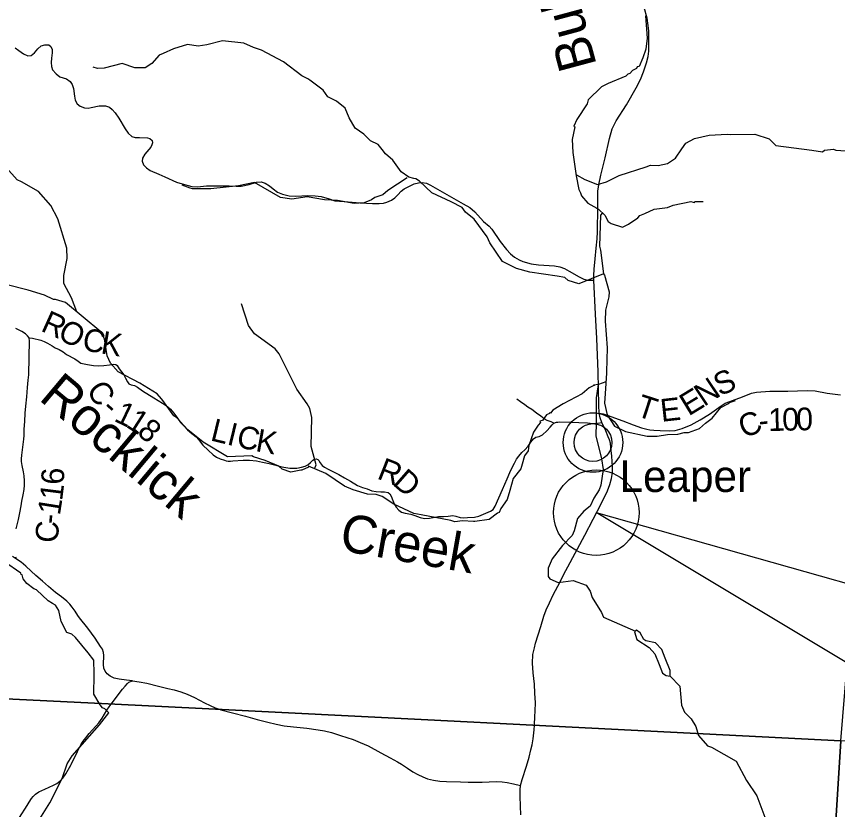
# Model space of a CAD drawing. Extents: x -1.8 to 75.7, y -2 to 25.
# Drawn here: x 45.89 to 47.944, y 18.595 to 20.577 of the extents above; entities that cross this region are included whole.
import ezdxf

# ---------------------------------------------------------------- set-up
doc = ezdxf.new("R2010")
doc.units = 0
for name, color, linetype in [('GM_X_County_Road', 7, 'Continuous'), ('GM_X_County_Road_Text', 7, 'Continuous'), ('GM_X_Minor_River', 7, 'Continuous'), ('GM_X_Minor_River_Text', 7, 'Continuous'), ('GM_X_State_Route', 7, 'Continuous'), ('GM_X_Township', 7, 'Continuous'), ('GM_X_Township_Road', 7, 'Continuous'), ('GM_X_Unincorporated', 7, 'Continuous'), ('GM_X_Unincorporated_Location', 7, 'Continuous'), ('GM_X_Unincorporated_Text', 7, 'Continuous'), ('TX_P_1', 7, 'Continuous')]:
    doc.layers.add(name, color=color, linetype=linetype)

msp = doc.modelspace()

# ---------------------------------------------------------------- linework, layer by layer
at = {"layer": 'GM_X_County_Road'}
for points in [[(45.8872, 20.4988), (45.896, 20.4924), (45.9077, 20.4835), (45.9186, 20.4785), (45.9274, 20.48), (45.9355, 20.4864), (45.9442, 20.4963), (45.9524, 20.5034), (45.9615, 20.5067), (45.9714, 20.5059), (45.9767, 20.5018), (45.9795, 20.495), (45.9799, 20.4864), (45.9784, 20.4734), (45.9773, 20.4621), (45.9784, 20.4521), (45.9805, 20.444), (45.9895, 20.4335), (45.9991, 20.4262), (46.0153, 20.4211), (46.0247, 20.4143), (46.0301, 20.4073), (46.033, 20.3968), (46.0352, 20.3782), (46.0373, 20.368), (46.0424, 20.3588), (46.0497, 20.3528), (46.0604, 20.3492), (46.0696, 20.3481), (46.0772, 20.3494), (46.0977, 20.3539), (46.1129, 20.3541), (46.1229, 20.3509), (46.1302, 20.3451), (46.1376, 20.3366), (46.1462, 20.3227), (46.1622, 20.296), (46.1699, 20.2854), (46.1791, 20.2775), (46.1874, 20.2751), (46.1978, 20.2743), (46.2185, 20.274), (46.2243, 20.2719), (46.2296, 20.2672), (46.2307, 20.261), (46.2294, 20.2561), (46.2262, 20.2506), (46.2113, 20.2331), (46.2055, 20.2228), (46.2051, 20.2158), (46.2081, 20.2066), (46.2158, 20.1985), (46.2247, 20.1923), (46.2463, 20.1831), (46.2614, 20.1761), (46.2909, 20.1633), (46.3103, 20.1571), (46.3287, 20.1524), (46.3432, 20.1511), (46.3656, 20.1537), (46.3949, 20.1543), (46.4224, 20.1543), (46.4399, 20.1532), (46.4525, 20.153), (46.4723, 20.1575), (46.4911, 20.1633), (46.5024, 20.1639), (46.5127, 20.1607), (46.5229, 20.1541), (46.5323, 20.1464), (46.543, 20.1383), (46.5556, 20.1332), (46.5725, 20.1291), (46.5893, 20.1283), (46.6192, 20.1295), (46.6378, 20.1289), (46.6521, 20.1274), (46.6726, 20.1216), (46.6865, 20.1161), (46.7101, 20.115), (46.7503, 20.1118), (46.7808, 20.1101), (46.7975, 20.1101), (46.8083, 20.1108), (46.8167, 20.1129), (46.8286, 20.1184), (46.8363, 20.1238), (46.8442, 20.1315), (46.8524, 20.1402), (46.8596, 20.146), (46.8749, 20.1539), (46.8854, 20.1586), (46.8959, 20.1618), (46.9048, 20.162), (46.9161, 20.1603), (46.9257, 20.1558), (47.0077, 20.1093), (47.0239, 20.0997), (47.0367, 20.0892), (47.0581, 20.0646), (47.0728, 20.0531), (47.079, 20.0459), (47.1001, 20.0151), (47.1157, 19.9944), (47.1258, 19.9837), (47.136, 19.9756), (47.1477, 19.9688), (47.1571, 19.965), (47.1772, 19.959), (47.1962, 19.9566), (47.2361, 19.9543), (47.2494, 19.9511), (47.2609, 19.947), (47.2728, 19.9408), (47.2976, 19.9261), (47.3091, 19.9208), (47.3185, 19.918), (47.3347, 19.9185)], [(45.8896, 19.2966), (45.8953, 19.3199), (45.8993, 19.3366), (45.9019, 19.3538), (45.9037, 19.3661), (45.9069, 19.3817), (45.9094, 19.3947), (45.9107, 19.4055), (45.9109, 19.4163), (45.9094, 19.4289), (45.908, 19.4387), (45.9045, 19.4553), (45.9032, 19.4645), (45.903, 19.4717), (45.9036, 19.4808), (45.9052, 19.4938), (45.9072, 19.5076), (45.9091, 19.521), (45.9096, 19.5299), (45.9098, 19.5457), (45.9111, 19.5648), (45.912, 19.5859), (45.9136, 19.6036), (45.916, 19.6262), (45.9182, 19.65), (45.9201, 19.6678), (45.921, 19.6815), (45.9215, 19.6949), (45.9219, 19.7123), (45.9222, 19.7368), (45.9231, 19.7556), (45.9231, 19.7657), (45.922, 19.7736), (45.9182, 19.7793), (45.9132, 19.7843), (45.9035, 19.7901), (45.889, 19.7969)], [(45.922, 19.7736), (45.9308, 19.773), (45.9516, 19.7678), (45.9595, 19.7651), (45.9679, 19.761), (45.9796, 19.754), (45.9873, 19.7494), (45.997, 19.7449), (46.0074, 19.7386), (46.016, 19.7323), (46.0361, 19.7217), (46.0449, 19.7154), (46.0512, 19.7106), (46.0682, 19.707), (46.0835, 19.7047), (46.0944, 19.7036), (46.1091, 19.705), (46.1228, 19.7061), (46.1339, 19.7081), (46.1386, 19.7072), (46.142, 19.7052), (46.1475, 19.6966), (46.1588, 19.6815), (46.1635, 19.6733), (46.1678, 19.6638), (46.1716, 19.6593), (46.1775, 19.6566), (46.1854, 19.6548), (46.1931, 19.6507), (46.2057, 19.6419), (46.2344, 19.6236), (46.2554, 19.6105), (46.2681, 19.602), (46.2758, 19.5959), (46.2841, 19.5859), (46.2929, 19.573), (46.3006, 19.5626), (46.309, 19.5538), (46.318, 19.5441), (46.3289, 19.5351), (46.3395, 19.5267), (46.3456, 19.5195), (46.3562, 19.5059), (46.3695, 19.4935), (46.3824, 19.4818), (46.3908, 19.4754), (46.4002, 19.4712), (46.4104, 19.4684), (46.4149, 19.4669), (46.4203, 19.4657), (46.426, 19.4657), (46.4314, 19.4664), (46.4572, 19.4682), (46.4734, 19.468), (46.4908, 19.4662), (46.5057, 19.4635), (46.5222, 19.4603), (46.536, 19.4569), (46.5475, 19.4529), (46.5595, 19.4504), (46.5742, 19.4483), (46.583, 19.4479), (46.592, 19.4483), (46.6035, 19.4511), (46.6121, 19.4533), (46.6187, 19.4567), (46.6255, 19.4626), (46.6316, 19.4678), (46.6354, 19.4703), (46.6397, 19.4712), (46.6438, 19.47), (46.6469, 19.4671), (46.6503, 19.4612), (46.6548, 19.4551), (46.6609, 19.4506), (46.67, 19.4459), (46.6837, 19.4393), (46.6968, 19.4328), (46.7108, 19.4244), (46.7258, 19.4156), (46.7432, 19.4052), (46.756, 19.3998), (46.7671, 19.3964), (46.7788, 19.3916), (46.7904, 19.3901), (46.8019, 19.3892), (46.8111, 19.3889), (46.8197, 19.3876), (46.8245, 19.3842), (46.8276, 19.3783), (46.8313, 19.3677), (46.8349, 19.3587), (46.8396, 19.3505), (46.8464, 19.3431), (46.8536, 19.3383), (46.8624, 19.3356), (46.8764, 19.3334), (46.8866, 19.3297), (46.9002, 19.325), (46.9105, 19.3225), (46.923, 19.3232), (46.946, 19.3275), (46.9584, 19.3275), (46.9702, 19.3286), (46.9815, 19.3295), (46.9896, 19.3284), (47, 19.3252), (47.0086, 19.3241), (47.0183, 19.3245), (47.0359, 19.3255), (47.0471, 19.3282), (47.0759, 19.3404), (47.0827, 19.3453), (47.0876, 19.353), (47.0878, 19.3534)], [(47.348, 19.5859), (47.3576, 19.5843), (47.3678, 19.581), (47.4068, 19.5663), (47.433, 19.5568), (47.4537, 19.549), (47.4665, 19.5453), (47.4746, 19.5438), (47.4843, 19.5428), (47.5001, 19.5421), (47.523, 19.5414), (47.5375, 19.5425), (47.5552, 19.547), (47.5774, 19.5567), (47.6006, 19.5688), (47.6235, 19.583), (47.6526, 19.604), (47.6628, 19.6106), (47.681, 19.6172), (47.7061, 19.6269), (47.7283, 19.6357), (47.7415, 19.6385), (47.7744, 19.6404), (47.7992, 19.6404), (47.8193, 19.6406), (47.8678, 19.6421), (47.8877, 19.6414), (47.9182, 19.6359), (47.9508, 19.6317)], [(47.0878, 19.3534), (47.1062, 19.3953), (47.1175, 19.4219), (47.1242, 19.4375), (47.131, 19.4517), (47.136, 19.461), (47.141, 19.4703), (47.1466, 19.4786), (47.1542, 19.487), (47.1615, 19.4937), (47.1699, 19.5035), (47.1766, 19.5134), (47.1832, 19.5215), (47.1895, 19.5254), (47.1972, 19.5274), (47.2056, 19.5319), (47.2164, 19.5419), (47.2248, 19.5507), (47.2304, 19.5563), (47.2346, 19.5606), (47.2413, 19.5632), (47.2441, 19.5636)], [(47.2441, 19.5636), (47.2493, 19.5641), (47.2755, 19.5628), (47.3181, 19.5612), (47.3327, 19.5601), (47.3434, 19.5608), (47.354, 19.5626)], [(46.1809, 18.9164), (46.1658, 18.9182), (46.1475, 18.9206), (46.1344, 18.9236), (46.1244, 18.9283), (46.1176, 18.9342), (46.1127, 18.9405), (46.1093, 18.9484), (46.1082, 18.9577), (46.1091, 18.9796), (46.1084, 18.9877), (46.1054, 18.9956), (46.1007, 19.0026), (46.0869, 19.0237), (46.0693, 19.0481), (46.0485, 19.0745), (46.044, 19.0801), (46.037, 19.091), (46.03, 19.1011), (46.0237, 19.1084), (46.0164, 19.1156), (46.0031, 19.1264), (45.9884, 19.1377), (45.9706, 19.1526), (45.9552, 19.1655), (45.939, 19.18), (45.927, 19.1906), (45.9137, 19.203), (45.9021, 19.213), (45.8908, 19.2209), (45.8807, 19.2274)], [(45.8908, 19.2209), (45.8885, 19.2259)]]:
    msp.add_lwpolyline(points, dxfattribs=at)
at = {"layer": 'GM_X_Minor_River'}
for points in [[(47.4634, 20.5784), (47.4676, 20.5233), (47.4646, 20.4952), (47.4571, 20.4742), (47.4473, 20.4522), (47.4424, 20.451), (47.4408, 20.4468), (47.4314, 20.4423), (47.4242, 20.4343), (47.4197, 20.4327), (47.4144, 20.4278), (47.3698, 20.4094), (47.3532, 20.4014), (47.3203, 20.369), (47.3173, 20.3587), (47.292, 20.3199), (47.2845, 20.3031), (47.2868, 20.3013), (47.28, 20.2701), (47.2815, 20.2374), (47.2903, 20.1785), (47.2968, 20.145), (47.3009, 20.1367), (47.3036, 20.1287), (47.3195, 20.1105), (47.3422, 20.098), (47.346, 20.0957), (47.3619, 20.0809), (47.3698, 20.0646), (47.3774, 20.0601), (47.4057, 20.051), (47.4208, 20.0583), (47.4446, 20.0735), (47.4496, 20.08), (47.4616, 20.085), (47.4855, 20.0957), (47.5183, 20.0995), (47.5323, 20.1053), (47.5773, 20.1145), (47.583, 20.1134), (47.5864, 20.1123), (47.5871, 20.1145), (47.6079, 20.1146)], [(47.3582, 19.9338), (47.297, 19.9092), (47.2704, 19.9176), (47.2616, 19.9247), (47.2428, 19.9284), (47.1739, 19.9378), (47.1409, 19.9476), (47.1056, 19.965), (47.0744, 20.0112), (47.0673, 20.0266), (47.035, 20.0702), (47.0136, 20.0884), (47.0049, 20.0997), (46.9777, 20.1138), (46.9293, 20.1366), (46.8984, 20.1657), (46.8888, 20.1713), (46.8843, 20.1722), (46.8719, 20.1753), (46.8526, 20.1892), (46.832, 20.2184), (46.8132, 20.2341), (46.8052, 20.2447), (46.7946, 20.2568), (46.776, 20.2665), (46.7595, 20.283), (46.7376, 20.2981), (46.7225, 20.324), (46.7127, 20.3479), (46.6905, 20.3653), (46.6689, 20.3762), (46.6573, 20.3933), (46.6241, 20.4183), (46.6189, 20.4215), (46.604, 20.4292), (46.5582, 20.4637), (46.5035, 20.4932), (46.4829, 20.4999), (46.459, 20.5102), (46.4055, 20.5164), (46.3663, 20.5063), (46.3447, 20.5032), (46.3179, 20.5071), (46.2828, 20.496), (46.2572, 20.4843), (46.2472, 20.4808), (46.2288, 20.4594), (46.2126, 20.4485), (46.1865, 20.4486), (46.1547, 20.4598), (46.1094, 20.4476), (46.0935, 20.4474), (46.0823, 20.4508)], [(46.0414, 19.839), (46.0278, 19.8743), (46.0086, 19.9099), (46.0089, 19.9301), (46.0173, 19.9723), (46.0164, 19.9977), (45.9943, 20.0717), (45.9767, 20.105), (45.9457, 20.1394), (45.903, 20.1635), (45.8924, 20.1687), (45.8649, 20.1993), (45.8452, 20.2566), (45.8334, 20.3112), (45.834, 20.3507)], [(47.2909, 20.1815), (47.3121, 20.17), (47.3438, 20.1572), (47.3656, 20.1637), (47.3978, 20.1798), (47.4653, 20.2016), (47.4764, 20.2054), (47.4953, 20.2048), (47.5189, 20.2093), (47.5386, 20.2231), (47.554, 20.2466), (47.5646, 20.2603), (47.5858, 20.2722), (47.6227, 20.2809), (47.6674, 20.2828), (47.6757, 20.2822), (47.7373, 20.2833), (47.7729, 20.2715), (47.7894, 20.2543), (47.8794, 20.2434), (47.9061, 20.2388), (47.9115, 20.2428), (47.9339, 20.2458), (47.9398, 20.243), (47.9761, 20.2407)], [(46.8677, 20.1739), (46.8191, 20.142), (46.807, 20.131), (46.7864, 20.1245), (46.7783, 20.1187), (46.7603, 20.1113), (46.7346, 20.1094), (46.6929, 20.1176), (46.6608, 20.119), (46.6171, 20.1261), (46.5792, 20.1208), (46.5506, 20.1248), (46.4856, 20.1626), (46.4456, 20.1536), (46.3762, 20.1467), (46.3309, 20.1466), (46.3245, 20.1479), (46.3051, 20.1554)], [(47.3564, 20.086), (47.3513, 20.0802), (47.3485, 20.0032)], [(47.3485, 20.0032), (47.351, 19.9935), (47.3582, 19.9338), (47.3609, 19.9304), (47.3726, 19.889), (47.3715, 19.8764), (47.3636, 19.8433), (47.3629, 19.816), (47.3679, 19.7491), (47.3664, 19.689), (47.3661, 19.6856), (47.3627, 19.635), (47.3612, 19.6111), (47.3673, 19.5818), (47.3859, 19.5533), (47.4138, 19.5401), (47.4675, 19.5281), (47.4925, 19.5285), (47.5182, 19.5327), (47.5443, 19.5328), (47.5601, 19.537), (47.5707, 19.5374), (47.5987, 19.5477), (47.6134, 19.5603), (47.63, 19.5729), (47.6523, 19.5996), (47.6697, 19.6091), (47.6735, 19.6125), (47.689, 19.6175)], [(46.0134, 19.8623), (45.988, 19.8697), (45.9834, 19.8701), (45.9607, 19.8807), (45.9195, 19.8935), (45.8636, 19.9071), (45.8382, 19.9116), (45.8212, 19.9184), (45.8106, 19.9275), (45.8019, 19.9354), (45.7928, 19.9536), (45.7898, 19.9552), (45.7906, 19.9529)], [(47.3647, 19.6644), (47.3464, 19.6574), (47.3332, 19.6558), (47.3359, 19.6559), (47.3226, 19.6494), (47.3053, 19.6341), (47.258, 19.6093), (47.232, 19.5933), (47.2259, 19.5857), (47.2244, 19.5876), (47.2233, 19.5845), (47.2157, 19.5818), (47.2059, 19.5677), (47.1995, 19.5658), (47.2006, 19.5624), (47.195, 19.5559), (47.1931, 19.5533), (47.1836, 19.5384), (47.172, 19.5046), (47.1697, 19.4912), (47.161, 19.4787), (47.1554, 19.4581), (47.1516, 19.4463), (47.1327, 19.4227), (47.1244, 19.3923), (47.1173, 19.3695), (47.1018, 19.3478), (47.0977, 19.3371), (47.0935, 19.3356), (47.0727, 19.3196), (47.0364, 19.3149), (47.0338, 19.3149), (47.0058, 19.3168), (46.9865, 19.3144), (46.9771, 19.3171), (46.9026, 19.3317), (46.8845, 19.3347), (46.8341, 19.3586), (46.8054, 19.3775), (46.7899, 19.3828), (46.7687, 19.3835), (46.7324, 19.3937), (46.7112, 19.4035), (46.664, 19.4349), (46.6208, 19.4531), (46.6208, 19.4508), (46.6038, 19.4435), (46.6012, 19.4432), (46.577, 19.4382), (46.5551, 19.4457), (46.5467, 19.4529), (46.5127, 19.4677), (46.4836, 19.4763), (46.4787, 19.479), (46.4182, 19.4769), (46.3573, 19.5129), (46.3191, 19.544), (46.2903, 19.5747), (46.2843, 19.5789), (46.2566, 19.6172), (46.2532, 19.6214), (46.2423, 19.6339), (46.1988, 19.6608), (46.1447, 19.6892), (46.1254, 19.7108), (46.1174, 19.729), (46.1106, 19.7716), (46.1018, 19.7887), (46.0134, 19.8623)], [(46.636, 19.4467), (46.6399, 19.4567), (46.6271, 19.5022), (46.6293, 19.5752), (46.6242, 19.5972), (46.6173, 19.6093), (46.5913, 19.646), (46.5475, 19.7342), (46.5371, 19.7467), (46.4857, 19.7841), (46.4707, 19.8052), (46.4533, 19.8591)], [(47.3449, 19.6572), (47.3398, 19.6241), (47.3398, 19.5618), (47.3396, 19.5292), (47.3537, 19.4714), (47.3575, 19.445), (47.3521, 19.4061), (47.348, 19.3941), (47.3345, 19.3729), (47.3252, 19.353), (47.309, 19.341), (47.2937, 19.3225), (47.2848, 19.2913), (47.2799, 19.2797), (47.2561, 19.2553), (47.2302, 19.222), (47.22, 19.1984), (47.2198, 19.1935), (47.2205, 19.1771), (47.2245, 19.1713), (47.2454, 19.1627), (47.2829, 19.1672), (47.3151, 19.1559), (47.3249, 19.1411), (47.33, 19.125), (47.3531, 19.0874), (47.3588, 19.0762), (47.4383, 19.0409)], [(45.9236, 18.5316), (45.9737, 18.6119), (46.0051, 18.6724), (46.0171, 18.7093), (46.0296, 18.7291), (46.0979, 18.8064), (46.1213, 18.8369), (46.1111, 18.8471), (46.1055, 18.849), (46.1001, 18.8566), (46.0839, 18.8832), (46.0846, 18.9314), (46.085, 18.9352), (46.0838, 18.9687), (46.0698, 18.9869), (46.0384, 19.0248), (46.0289, 19.0336), (46.0164, 19.0373), (46.002, 19.0647), (45.9967, 19.0924), (45.988, 19.1057), (45.9804, 19.1102), (45.9698, 19.1163), (45.9407, 19.1443), (45.9343, 19.1466), (45.9161, 19.1599), (45.9074, 19.172), (45.9048, 19.1815), (45.9021, 19.1826), (45.9017, 19.186), (45.8605, 19.2145)], [(47.4422, 19.02), (47.4725, 18.9997), (47.4868, 18.9844), (47.4977, 18.9575), (47.5057, 18.9356), (47.515, 18.9296), (47.5252, 18.9281), (47.5249, 18.9426), (47.5126, 18.973), (47.5041, 18.9949), (47.4888, 19.0113), (47.464, 19.0167), (47.4592, 19.0203), (47.4502, 19.0365), (47.441, 19.0432), (47.4363, 19.0392), (47.4422, 19.02)], [(47.5252, 18.9281), (47.549, 18.9035), (47.5532, 18.8555), (47.561, 18.8381), (47.5775, 18.8213), (47.589, 18.8023), (47.5963, 18.7801), (47.6182, 18.7539), (47.6284, 18.7505)], [(47.6284, 18.7505), (47.6904, 18.7156), (47.7165, 18.6675), (47.7418, 18.6293), (47.7619, 18.5758), (47.7722, 18.5049), (47.7784, 18.4791), (47.7861, 18.4628)]]:
    msp.add_lwpolyline(points, dxfattribs=at)
at = {"layer": 'GM_X_State_Route'}
for points in [[(47.1511, 18.6554), (47.1552, 18.6701), (47.1656, 18.7036), (47.1726, 18.7261), (47.1769, 18.7442), (47.1798, 18.7566), (47.1827, 18.7718), (47.185, 18.7939), (47.186, 18.8058), (47.1861, 18.8077), (47.1868, 18.8267), (47.1875, 18.842), (47.1882, 18.8615), (47.1868, 18.8856), (47.1859, 18.9087), (47.1825, 18.9367), (47.1807, 18.9609), (47.1821, 18.9828), (47.1857, 18.9993), (47.1886, 19.0108), (47.2017, 19.0526), (47.2092, 19.0781), (47.2148, 19.0941), (47.2232, 19.1118), (47.2329, 19.1314), (47.2498, 19.1644), (47.2593, 19.1829), (47.2692, 19.2014), (47.3117, 19.2807), (47.3538, 19.3607), (47.3688, 19.3914), (47.3745, 19.4072), (47.3788, 19.4221), (47.3811, 19.437), (47.3811, 19.4513), (47.3791, 19.4778), (47.3769, 19.5), (47.3758, 19.5104), (47.3736, 19.5189), (47.3702, 19.5268), (47.364, 19.5413), (47.354, 19.5626), (47.35, 19.5741), (47.348, 19.5859), (47.3472, 19.6061), (47.3449, 19.6886), (47.3418, 19.7725), (47.3383, 19.8331), (47.3347, 19.9185), (47.3347, 19.9299), (47.3355, 19.9459), (47.3377, 19.9712), (47.3403, 19.9979), (47.3428, 20.0215), (47.3435, 20.039), (47.344, 20.1002), (47.344, 20.1211), (47.3447, 20.1408), (47.3466, 20.1561), (47.352, 20.1802), (47.3627, 20.2237), (47.3732, 20.2725), (47.3802, 20.2961), (47.3904, 20.3163), (47.4157, 20.3566), (47.4404, 20.3991), (47.4507, 20.4196), (47.4584, 20.4392), (47.4662, 20.4611), (47.4703, 20.4774), (47.4718, 20.4905), (47.4718, 20.5155), (47.4716, 20.5406), (47.4706, 20.5544), (47.4679, 20.5727), (47.4604, 20.5999)], [(46.0261, 18.7056), (46.0272, 18.7074), (46.0431, 18.7397), (46.0511, 18.7564), (46.057, 18.7657), (46.0637, 18.7746), (46.0724, 18.7851), (46.0893, 18.8033), (46.0961, 18.8117), (46.1045, 18.8235), (46.1161, 18.8432), (46.1222, 18.8518), (46.1274, 18.8586), (46.1296, 18.8614), (46.1554, 18.896), (46.1621, 18.9034), (46.1681, 18.9101), (46.1719, 18.9133), (46.1809, 18.9164)], [(46.1809, 18.9164), (46.1976, 18.9145), (46.2166, 18.9107), (46.2455, 18.9037), (46.2694, 18.8976), (46.2846, 18.8942), (46.3017, 18.8892), (46.3171, 18.8836), (46.3354, 18.8748), (46.3609, 18.8619), (46.3747, 18.8549), (46.3876, 18.8495), (46.3996, 18.8452), (46.4014, 18.8445), (46.431, 18.8368), (46.4633, 18.8285), (46.4922, 18.8203), (46.5188, 18.8131), (46.5403, 18.8081), (46.5602, 18.8045), (46.5832, 18.8018), (46.6166, 18.798), (46.6451, 18.7946), (46.6609, 18.7919), (46.6783, 18.7874), (46.7007, 18.7804), (46.7325, 18.7697), (46.7499, 18.7627), (46.7698, 18.7542), (46.8019, 18.7365), (46.8249, 18.7246), (46.843, 18.7144), (46.8532, 18.7085), (46.8685, 18.6981), (46.8821, 18.6896), (46.8941, 18.6825), (46.9067, 18.6767), (46.9184, 18.6719), (46.9334, 18.6683), (46.9489, 18.6661), (46.9659, 18.6649), (47.0009, 18.6645), (47.0199, 18.6638), (47.0373, 18.6638), (47.0547, 18.6638), (47.0901, 18.6652), (47.105, 18.6645), (47.1179, 18.6624), (47.1333, 18.6593), (47.1511, 18.6554)], [(45.9172, 18.6054), (45.9225, 18.6137), (45.928, 18.6223), (45.9322, 18.6274), (45.9377, 18.6333), (45.9463, 18.6392), (45.9613, 18.6462), (45.9827, 18.6555), (45.9918, 18.6603), (45.9989, 18.6658), (46.0061, 18.6734), (46.0137, 18.6846), (46.0261, 18.7056)], [(47.1517, 18.5815), (47.151, 18.6034), (47.15, 18.6282), (47.1503, 18.6441), (47.1511, 18.6554)], [(45.8978, 18.575), (45.9172, 18.6054)]]:
    msp.add_lwpolyline(points, dxfattribs=at)
at = {"layer": 'GM_X_Township'}
for points in [[(43.8002, 18.978), (44.8356, 18.9224), (45.3865, 18.8952), (46.1197, 18.859), (46.3714, 18.8466), (46.9192, 18.8195), (47.1815, 18.806), (47.9522, 18.7663), (48.0201, 19.5982), (48.0214, 19.6198), (48.0228, 19.6698), (48.0235, 19.6926), (48.0261, 19.7186), (48.0301, 19.7636), (48.0891, 20.7799), (48.1186, 21.2763), (48.1494, 21.7937), (48.1876, 22.5121)], [(47.7632, 15.7121), (47.7893, 16.1371), (47.8138, 16.5363), (47.826, 16.7363), (47.8708, 17.4759), (47.8899, 17.791), (47.9266, 18.366), (47.9522, 18.7663), (47.1815, 18.806), (46.9192, 18.8195), (46.3714, 18.8466), (46.1197, 18.859), (45.3865, 18.8952), (44.8356, 18.9224), (43.8002, 18.978)], [(50.6002, 18.6397), (50.591, 18.6401), (50.1896, 18.6602), (49.0051, 18.7193), (48.8964, 18.7242), (47.9522, 18.7663), (47.9266, 18.366), (47.8899, 17.791), (47.8708, 17.4759), (47.826, 16.7363), (47.8138, 16.5363), (47.7893, 16.1371), (47.7632, 15.7121)]]:
    msp.add_lwpolyline(points, dxfattribs=at)
at = {"layer": 'GM_X_Township_Road'}
msp.add_lwpolyline([(47.2346, 19.5606), (47.2275, 19.564), (47.218, 19.5674), (47.2101, 19.5719), (47.2017, 19.5778), (47.1907, 19.5857), (47.1789, 19.5945), (47.1694, 19.601), (47.1617, 19.6065), (47.1513, 19.6142), (47.1419, 19.6205)], dxfattribs=at)
at = {"layer": 'GM_X_Unincorporated'}
for radius in [0.0744, 0.0472]:
    msp.add_circle((47.3322, 19.5123), radius, dxfattribs=at)
at = {"layer": 'GM_X_Unincorporated_Location'}
msp.add_line((47.3322, 19.5123), (47.3322, 19.5123), dxfattribs=at)
at = {"layer": 'TX_P_1'}
msp.add_lwpolyline([(48.142, 18.8568), (47.3404, 19.337), (48.142, 19.1111)], dxfattribs=at)
msp.add_circle((47.3404, 19.337), 0.107, dxfattribs=at)

# ---------------------------------------------------------------- texts
at = {"layer": 'GM_X_County_Road_Text'}
for s, rotation, p in [('R', 335.7221, (45.9488, 19.7924)), ('O', 332.0338, (45.9905, 19.7736)), ('C', 349.6234, (46.0526, 19.7439)), ('K', 350.4358, (46.0993, 19.7354)), ('S', 23.6824, (47.6491, 19.6273)), ('N', 33.8168, (47.6098, 19.6008)), ('C', 303.6154, (46.0636, 19.6432)), ('T', 341.992, (47.4372, 19.5797)), ('E', 31.3233, (47.5713, 19.5772)), ('E', 6.3632, (47.5036, 19.5639)), ('-', 318.5246, (46.1, 19.5922)), ('1', 334.5372, (46.1319, 19.5672)), ('1', 327.2301, (46.1618, 19.553)), ('1', 1.2465, (47.7708, 19.5409)), ('0', 1.2387, (47.8058, 19.5417)), ('0', 1.2308, (47.8408, 19.5424)), ('8', 318.2232, (46.1893, 19.5355)), ('L', 346.3286, (46.3732, 19.518)), ('C', 21.0284, (47.7092, 19.5224)), ('I', 346.3273, (46.4145, 19.5079)), ('C', 347.0681, (46.4379, 19.5022)), ('-', 6.6661, (47.7491, 19.5383)), ('K', 349.7534, (46.4863, 19.4912)), ('R', 338.3562, (46.7897, 19.4231)), ('D', 318.7764, (46.8287, 19.4085)), ('6', 89.1677, (46.0094, 19.4068)), ('1', 82.8945, (46.0046, 19.3653)), ('1', 81.0335, (45.9989, 19.3287)), ('-', 84.6766, (45.9969, 19.3065)), ('C', 86.3678, (45.9939, 19.2603))]:
    msp.add_text(s, height=0.0568, rotation=rotation, dxfattribs=at).set_placement(p)
at = {"layer": 'GM_X_Minor_River_Text'}
for s, height, rotation, p in [('Bullskin', 0.09471, 105.0011, (47.3421, 20.4554)), ('Rocklick', 0.0947, 319.9998, (45.9438, 19.6205)), ('Creek', 0.0947, 349.9986, (46.6953, 19.2435))]:
    msp.add_text(s, height=height, rotation=rotation, dxfattribs=at).set_placement(p)
at = {"layer": 'GM_X_Unincorporated_Text'}
msp.add_text('Leaper', height=0.07898, rotation=0, dxfattribs=at).set_placement((47.3987, 19.3887))

doc.saveas('drawing.dxf')
